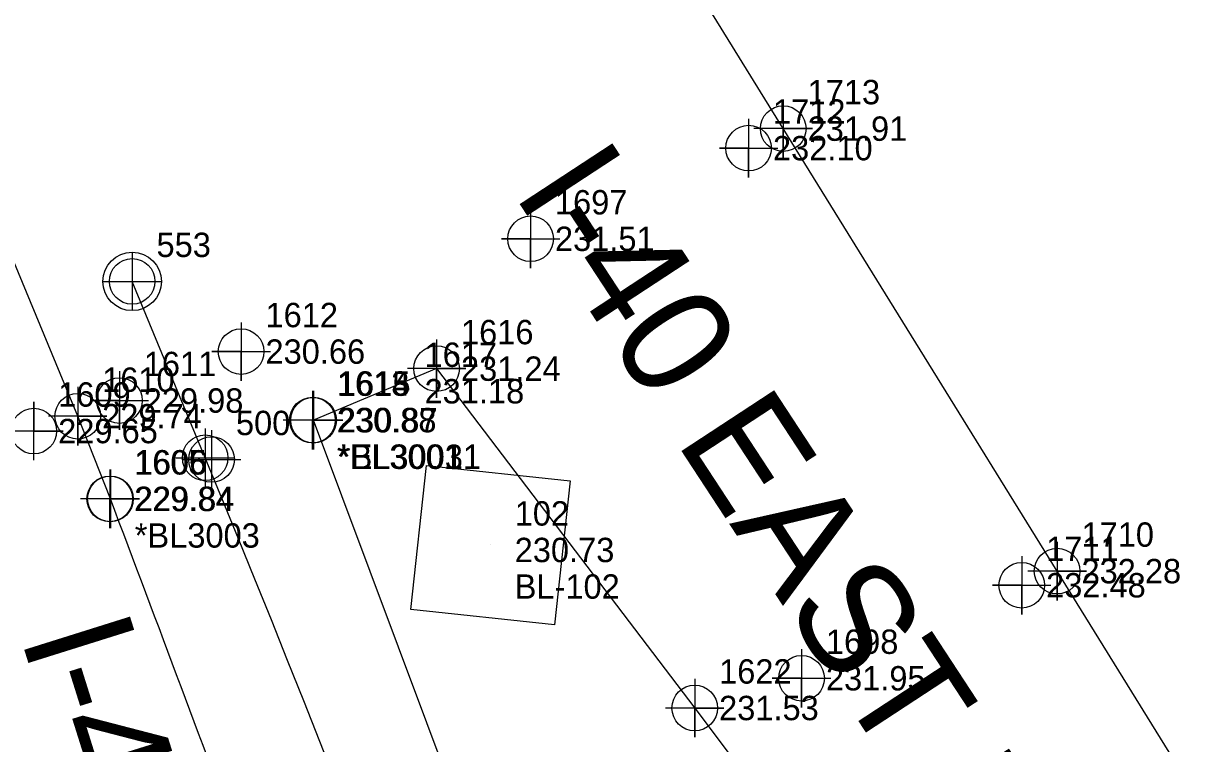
# Model space of a CAD drawing. Extents: x 2130621 to 2131998, y 642516 to 644503.
# Drawn here: x 2131082.6 to 2131203.6, y 643963 to 644036.8 of the extents above; entities that cross this region are included whole.
import ezdxf

# ---------------------------------------------------------------- set-up
doc = ezdxf.new("R2010")
doc.units = 0
for name, color, linetype in [('Cogo Default Point CELL', 7, 'Continuous'), ('COGO Default Point Number', 7, 'Continuous'), ('CTL Secondary Horizontal and Vertical CELL', 7, 'Continuous'), ('CTL Secondary Horizontal and Vertical Cogo Comment', 7, 'Continuous'), ('CTL Secondary Horizontal and Vertical Cogo Elevation', 7, 'Continuous'), ('CTL Secondary Horizontal and Vertical Cogo Number', 7, 'Continuous'), ('Exist Other Culture Sign Cogo Elevation', 7, 'Continuous'), ('Exist Other Culture Sign Cogo Number', 7, 'Continuous'), ('Exist Roads EOP', 7, 'Continuous'), ('Exist Roads EOP Cogo Comment', 7, 'Continuous'), ('Exist Roads EOP Cogo Elevation', 7, 'Continuous'), ('Exist Roads EOP Cogo Number', 7, 'Continuous'), ('Exist Roads EOP Cogo Point CELL', 7, 'Continuous'), ('Exist Roads EOP Other Cogo Comment', 7, 'Continuous'), ('Exist Roads EOP Other Cogo Elevation', 7, 'Continuous'), ('Exist Roads EOP Other Cogo Number', 7, 'Continuous'), ('Exist Roads EOP Other Cogo Point CELL', 7, 'Continuous'), ('Exist Roads EOT Cogo Elevation', 7, 'Continuous'), ('Exist Roads EOT Cogo Number', 7, 'Continuous'), ('Exist Roads EOT Cogo Point CELL', 7, 'Continuous'), ('Exist Roads EOT Text', 7, 'Continuous'), ('Exist Roads Soil Cogo Elevation', 7, 'Continuous'), ('Exist Roads Soil Cogo Number', 7, 'Continuous'), ('Exist Roads Soil Cogo Point CELL', 7, 'Continuous'), ('Prop Horizontal Alignment', 7, 'Continuous')]:
    doc.layers.add(name, color=color, linetype=linetype)

msp = doc.modelspace()

# ---------------------------------------------------------------- linework, layer by layer
at = {"layer": 'Cogo Default Point CELL'}
for points in [[(2131093.76, 644013.35), (2131093.76, 644010.35)], [(2131090.76, 644010.35), (2131093.76, 644010.35)], [(2131093.76, 644010.35), (2131096.76, 644010.35)], [(2131093.76, 644010.35), (2131093.76, 644007.35)], [(2131101.25, 643995.26), (2131101.25, 643992.26)], [(2131101.91, 643995.08), (2131101.91, 643992.08)], [(2131098.25, 643992.26), (2131101.25, 643992.26)], [(2131101.25, 643992.26), (2131104.25, 643992.26)], [(2131101.25, 643992.26), (2131101.25, 643989.26)], [(2131098.91, 643992.08), (2131101.91, 643992.08)], [(2131101.91, 643992.08), (2131104.91, 643992.08)], [(2131101.91, 643992.08), (2131101.91, 643989.08)]]:
    msp.add_lwpolyline(points, dxfattribs=at)
for centre in [(2131093.76, 644010.35), (2131101.25, 643992.26), (2131101.91, 643992.08)]:
    msp.add_circle(centre, 2.34, dxfattribs=at)
at = {"layer": 'CTL Secondary Horizontal and Vertical CELL'}
msp.add_line((2131130.48, 643983.33), (2131130.48, 643983.33), dxfattribs=at)
msp.add_lwpolyline([(2131123.96, 643991.47), (2131138.7, 643989.89), (2131137.11, 643975.12), (2131122.37, 643976.71)], close=True, dxfattribs=at)
at = {"layer": 'Exist Roads EOP'}
msp.add_line((2131125, 644001.4), (2131112.37, 643996.12), dxfattribs=at)
for points in [[(2131269.83, 643849.54), (2131245.23, 643889.35), (2131216.18, 643936.13), (2131188.66, 643980.63), (2131160.56, 644026.02), (2131133.77, 644069.38), (2131106.56, 644113.29), (2131078.46, 644158.69), (2131052.15, 644201.1)], [(2131091.53, 643988.04), (2131088.18, 643996.52), (2131069.48, 644041.65), (2131049.16, 644087.39), (2131027.85, 644132.11), (2131005.29, 644177.62)], [(2131125, 644001.4), (2131151.48, 643966.59), (2131158.59, 643957.1), (2131179.44, 643923.18), (2131206.93, 643878.75), (2131233.55, 643835.75)], [(2131264.27, 643222.56), (2131259.88, 643269.33), (2131257.02, 643319.4), (2131254.26, 643369.65), (2131250.08, 643419.42), (2131246.15, 643469.03), (2131240.84, 643519.13), (2131234.37, 643568.56), (2131226.33, 643620.18), (2131217.03, 643668.71), (2131205.62, 643717.61), (2131192.06, 643767.26), (2131177.97, 643815.09), (2131162.29, 643862.93), (2131145.36, 643910.85), (2131126.91, 643957.29), (2131112.37, 643996.12)]]:
    msp.add_lwpolyline(points, dxfattribs=at)
msp.add_spline([(2131166.25, 643216.7), (2131171.81, 643218.72), (2131182.37, 643223.97), (2131191.81, 643231.15), (2131200.5, 643239.7), (2131208.81, 643249.07), (2131216.07, 643259), (2131218.72, 643264.35), (2131220.54, 643270.1), (2131222.84, 643282.01), (2131224.36, 643293.92), (2131224.88, 643317.79), (2131222.06, 643367.67), (2131218.54, 643416.81), (2131214.32, 643466.35), (2131209.17, 643515.67), (2131202.79, 643565.15), (2131195.05, 643613.99), (2131186.4, 643662.48), (2131176.01, 643711.41), (2131164.62, 643759.89), (2131151.87, 643807.85), (2131137.86, 643855.41), (2131122.57, 643902.86), (2131105.96, 643949.49), (2131091.53, 643988.04)], degree=3, dxfattribs=at)
at = {"layer": 'Exist Roads EOP Cogo Point CELL'}
for points in [[(2131112.26, 643999.12), (2131112.26, 643993.12), (2131112.26, 643996.12), (2131115.26, 643996.12), (2131109.26, 643996.12)], [(2131112.37, 643999.12), (2131112.37, 643993.12), (2131112.37, 643996.12), (2131115.37, 643996.12), (2131109.37, 643996.12)], [(2131091.46, 643991.04), (2131091.46, 643985.04), (2131091.46, 643988.04), (2131094.46, 643988.04), (2131088.46, 643988.04)]]:
    msp.add_lwpolyline(points, dxfattribs=at)
for centre in [(2131112.26, 643996.12), (2131112.37, 643996.12), (2131091.46, 643988.04)]:
    msp.add_circle(centre, 2.34, dxfattribs=at)
at = {"layer": 'Exist Roads EOP Other Cogo Point CELL'}
for points in [[(2131160.56, 644029.02), (2131160.56, 644023.02), (2131160.56, 644026.02), (2131163.56, 644026.02), (2131157.56, 644026.02)], [(2131125, 644004.4), (2131125, 643998.4), (2131125, 644001.4), (2131128, 644001.4), (2131122, 644001.4)], [(2131088.18, 643999.52), (2131088.18, 643993.52), (2131088.18, 643996.52), (2131091.18, 643996.52), (2131085.18, 643996.52)], [(2131112.37, 643999.11), (2131112.37, 643993.11), (2131112.37, 643996.11), (2131115.37, 643996.11), (2131109.37, 643996.11)], [(2131091.53, 643991.04), (2131091.53, 643985.04), (2131091.53, 643988.04), (2131094.53, 643988.04), (2131088.53, 643988.04)], [(2131188.66, 643983.63), (2131188.66, 643977.63), (2131188.66, 643980.63), (2131191.66, 643980.63), (2131185.66, 643980.63)], [(2131151.48, 643969.59), (2131151.48, 643963.59), (2131151.48, 643966.59), (2131154.48, 643966.59), (2131148.48, 643966.59)]]:
    msp.add_lwpolyline(points, dxfattribs=at)
for centre in [(2131160.56, 644026.02), (2131125, 644001.4), (2131088.18, 643996.52), (2131112.37, 643996.11), (2131091.53, 643988.04), (2131188.66, 643980.63), (2131151.48, 643966.59)]:
    msp.add_circle(centre, 2.34, dxfattribs=at)
at = {"layer": 'Exist Roads EOT Cogo Point CELL'}
for points in [[(2131157.01, 644027.02), (2131157.01, 644021.02), (2131157.01, 644024.02), (2131154.01, 644024.02), (2131160.01, 644024.02)], [(2131134.64, 644017.72), (2131134.64, 644011.72), (2131134.64, 644014.72), (2131131.64, 644014.72), (2131137.64, 644014.72)], [(2131104.94, 644006.15), (2131104.94, 644000.15), (2131104.94, 644003.15), (2131101.94, 644003.15), (2131107.94, 644003.15)], [(2131092.45, 644001.13), (2131092.45, 643995.13), (2131092.45, 643998.13), (2131089.45, 643998.13), (2131095.45, 643998.13)], [(2131185.03, 643982.18), (2131185.03, 643976.18), (2131185.03, 643979.18), (2131182.03, 643979.18), (2131188.03, 643979.18)], [(2131162.44, 643972.64), (2131162.44, 643966.64), (2131162.44, 643969.64), (2131159.44, 643969.64), (2131165.44, 643969.64)]]:
    msp.add_lwpolyline(points, dxfattribs=at)
for centre in [(2131157.01, 644024.02), (2131134.64, 644014.72), (2131104.94, 644003.15), (2131092.45, 643998.13), (2131185.03, 643979.18), (2131162.44, 643969.64)]:
    msp.add_circle(centre, 2.34, dxfattribs=at)
at = {"layer": 'Exist Roads Soil Cogo Point CELL'}
msp.add_lwpolyline([(2131083.67, 643992), (2131083.67, 643998), (2131083.67, 643995), (2131086.67, 643995), (2131080.67, 643995)], dxfattribs=at)
msp.add_circle((2131083.67, 643995), 2.34, dxfattribs=at)
at = {"layer": 'Prop Horizontal Alignment'}
msp.add_line((2131101.25, 643992.26), (2131093.76, 644010.35), dxfattribs=at)
msp.add_circle((2131093.76, 644010.35), 3, dxfattribs=at)
msp.add_arc((2129448.47, 643307.66), 1788.96, 4.14306, 22.49968, dxfattribs=at)

# ---------------------------------------------------------------- texts
at = {"layer": 'COGO Default Point Number'}
for s, p in [('553', (2131096.26, 644012.85)), ('500', (2131104.41, 643994.58))]:
    msp.add_text(s, height=2.5, dxfattribs=at).set_placement(p)
at = {"layer": 'CTL Secondary Horizontal and Vertical Cogo Comment'}
msp.add_text('BL-102', height=2.5, dxfattribs=at).set_placement((2131133.01, 643977.8))
at = {"layer": 'CTL Secondary Horizontal and Vertical Cogo Elevation'}
msp.add_text('230.73', height=2.5, dxfattribs=at).set_placement((2131133.01, 643981.55))
at = {"layer": 'CTL Secondary Horizontal and Vertical Cogo Number'}
msp.add_text('102', height=2.5, dxfattribs=at).set_placement((2131133.01, 643985.3))
at = {"layer": 'Exist Other Culture Sign Cogo Elevation'}
msp.add_text('231.18', height=2.5, dxfattribs=at).set_placement((2131123.76, 643997.83))
at = {"layer": 'Exist Other Culture Sign Cogo Number'}
msp.add_text('1617', height=2.5, dxfattribs=at).set_placement((2131123.76, 644001.58))
at = {"layer": 'Exist Roads EOP Cogo Comment'}
for s, p in [('*EL3001', (2131114.76, 643991.12)), ('*EL30011', (2131114.87, 643991.12))]:
    msp.add_text(s, height=2.5, dxfattribs=at).set_placement(p)
at = {"layer": 'Exist Roads EOP Cogo Elevation'}
for s, p in [('230.88', (2131114.76, 643994.87)), ('230.87', (2131114.87, 643994.87)), ('229.84', (2131093.96, 643986.79))]:
    msp.add_text(s, height=2.5, dxfattribs=at).set_placement(p)
at = {"layer": 'Exist Roads EOP Cogo Number'}
for s, p in [('1613', (2131114.76, 643998.62)), ('1614', (2131114.87, 643998.62)), ('1605', (2131093.96, 643990.54))]:
    msp.add_text(s, height=2.5, dxfattribs=at).set_placement(p)
at = {"layer": 'Exist Roads EOP Other Cogo Comment'}
for s, p in [('*BL30031', (2131114.87, 643991.11)), ('*BL3003', (2131094.03, 643983.04))]:
    msp.add_text(s, height=2.5, dxfattribs=at).set_placement(p)
at = {"layer": 'Exist Roads EOP Other Cogo Elevation'}
for s, p in [('231.91', (2131163.06, 644024.77)), ('231.24', (2131127.5, 644000.15)), ('229.74', (2131090.68, 643995.27)), ('230.87', (2131114.87, 643994.86)), ('229.84', (2131094.03, 643986.79)), ('232.28', (2131191.16, 643979.38)), ('231.53', (2131153.98, 643965.34))]:
    msp.add_text(s, height=2.5, dxfattribs=at).set_placement(p)
at = {"layer": 'Exist Roads EOP Other Cogo Number'}
for s, p in [('1713', (2131163.06, 644028.52)), ('1616', (2131127.5, 644003.9)), ('1610', (2131090.68, 643999.02)), ('1615', (2131114.87, 643998.61)), ('1606', (2131094.03, 643990.54)), ('1710', (2131191.16, 643983.13)), ('1622', (2131153.98, 643969.09))]:
    msp.add_text(s, height=2.5, dxfattribs=at).set_placement(p)
at = {"layer": 'Exist Roads EOT Cogo Elevation'}
for s, p in [('232.10', (2131159.51, 644022.77)), ('231.51', (2131137.14, 644013.47)), ('230.66', (2131107.44, 644001.9)), ('229.98', (2131094.95, 643996.88)), ('232.48', (2131187.53, 643977.93)), ('231.95', (2131164.94, 643968.39))]:
    msp.add_text(s, height=2.5, dxfattribs=at).set_placement(p)
at = {"layer": 'Exist Roads EOT Cogo Number'}
for s, p in [('1712', (2131159.51, 644026.52)), ('1697', (2131137.14, 644017.22)), ('1612', (2131107.44, 644005.65)), ('1611', (2131094.95, 644000.63)), ('1711', (2131187.53, 643981.68)), ('1698', (2131164.94, 643972.14))]:
    msp.add_text(s, height=2.5, dxfattribs=at).set_placement(p)
at = {"layer": 'Exist Roads EOT Text'}
for s, rotation, p in [('I-40 EAST BOUND LANE', 303.2392, (2131132.75, 644019.45)), ('I-40 EAST BOUND EXIT RAMP', 287.4395, (2131082.27, 643973.9))]:
    msp.add_text(s, height=11.3735, rotation=rotation, dxfattribs=at).set_placement(p)
at = {"layer": 'Exist Roads Soil Cogo Elevation'}
msp.add_text('229.65', height=2.5, dxfattribs=at).set_placement((2131086.17, 643993.75))
at = {"layer": 'Exist Roads Soil Cogo Number'}
msp.add_text('1609', height=2.5, dxfattribs=at).set_placement((2131086.17, 643997.5))

doc.saveas('drawing.dxf')
